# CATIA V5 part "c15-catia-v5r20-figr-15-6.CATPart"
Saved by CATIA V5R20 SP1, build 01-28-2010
Part number: Part1
Bounding box of the stored display mesh (mm): x -50 to 50, y -32.5 to 33.5, z -52 to 1
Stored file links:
  D:\v5_r20\psrt_files_downloaded\c15\c15-catia-v5r20-figr-15-6.CATPart
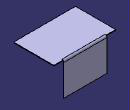
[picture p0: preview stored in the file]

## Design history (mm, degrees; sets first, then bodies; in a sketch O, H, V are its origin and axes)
SheetMetalParameters1: Thickness 1, BendRadius 2, KFactor 0.400515 {= log(min(100,max(20*SheetMetalParameters1.BendRadius,SheetMetalParameters1.Thickness)/SheetMetalParameters1.Thickness))/log(100)/2}, ReliefRadialLength 1, ReliefAxialLength 2, MinimumBendRadius 0
Body1 (main body)
  Sketch1 on xy-plane, origin (0, 0, 0), H (1, 0, 0), V (0, 1, 0)
    line L1 (-50, 32.5) -> (50, 32.5)
    line L2 (50, 32.5) -> (50, -32.5)
    line L3 (50, -32.5) -> (-50, -32.5)
    line L4 (-50, -32.5) -> (-50, 32.5)
    length L1 = 100
    length L2 = 65
    horizontal: L1 H, L3 H
    vertical: L2 V, L4 V
    symmetry: L4 L2 V, L1 L3 H
  Wall1: Thickness 1, Profile Sketch1
  d_NewWallOnEdge1: NewWallOnEdge_Edge edge [face of Wall1 | face of Wall1], NewWallOnEdge_Length 53, NewWallOnEdge_HeightLimitOffset 0, NewWallOnEdge_WidthOffset1 -15, NewWallOnEdge_WidthOffset2 -15, NewWallOnEdge_Angle 90, NewWallOnEdge_BendRadiusValue 2 {= SheetMetalParameters1.BendRadius}, NewWallOnEdge_BendTable SheetMetalParameters1, KFacteur 0.400515 {= log(min(100,max(20*d_NewWallOnEdge1.Radius,SheetMetalParameters1.Thickness)/SheetMetalParameters1.Thickness))/log(100)/2}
